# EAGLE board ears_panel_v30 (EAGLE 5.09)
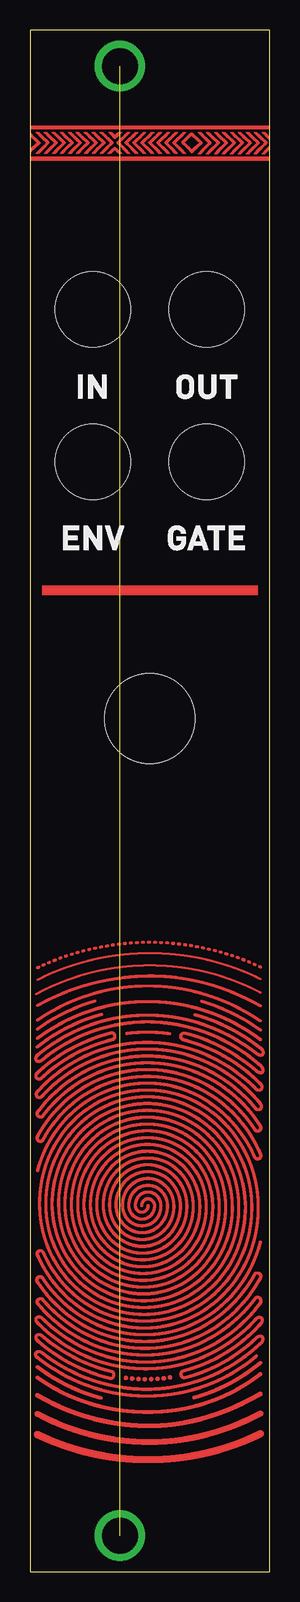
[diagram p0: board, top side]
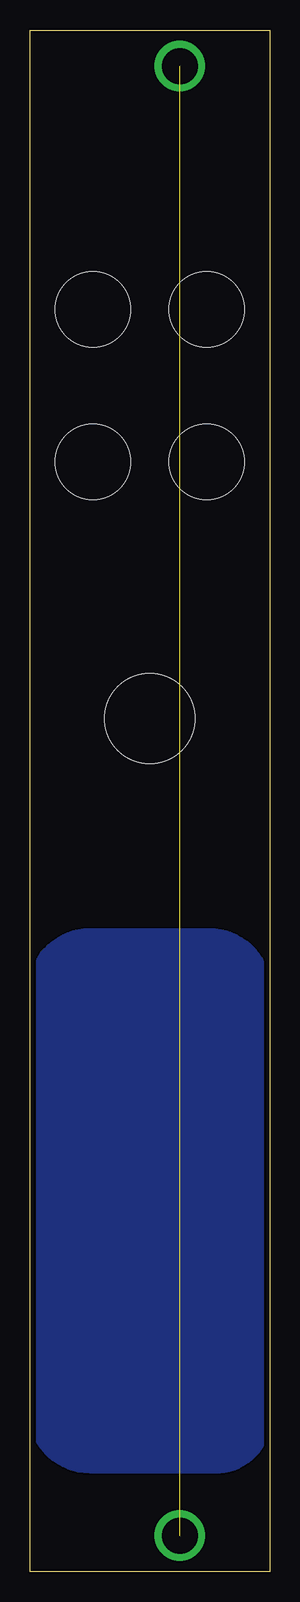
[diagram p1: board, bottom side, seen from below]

Size 20 x 128.5 mm. Coordinates in mm from the lower left corner, seen from the top.
Outline: 0,0 20,0 20,128.5 0,128.5 0,0
Copper layers (1*16): Top 0.035mm / dielectric 1.5mm / Bottom 0.035mm
Design rules "PCBCart-Standard *": minimum track width 8mil, minimum drill 0.4mm, track to track 8mil, track to pad 8mil, pad to pad 8mil, via to via 8mil, smd to smd 8mil, copper to edge 20mil, drill to drill 8mil, minimum pad ring 8mil, minimum via ring 10mil, stop-mask expansion 3mil, vias tented up to drill 25mil, thermal gap 8mil
Holes 6.3 mm at 5.25,92.5 14.75,92.5 5.25,105.2 14.75,105.2
Holes 7.5 mm at 10,71.1

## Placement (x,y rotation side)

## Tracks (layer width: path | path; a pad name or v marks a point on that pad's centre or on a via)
N$3  (via drill 3 pad 4.19)  (1 unrouted)
  other vias: 7.5,125.5 7.5,3
N$5
  pour Bottom: 0.01,48.4 arc-90 5.01,53.4 15.01,53.4 arc-90 20.01,48.4 20.01,13.4 arc-90 15.01,8.4 5.01,8.4 arc-90 0.01,12.4
(copper drawn outside any net)
  shapes: Top area x32567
